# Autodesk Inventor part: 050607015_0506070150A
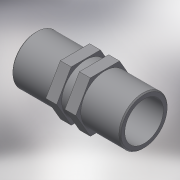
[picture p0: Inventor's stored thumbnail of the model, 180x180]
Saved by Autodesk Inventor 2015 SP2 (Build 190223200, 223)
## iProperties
Created: 2017-05
Part Number: 050607015_0506070150A
Material: Generic
Description: PLASSON NIPPLE 1.1/2"-1.1/2"
Document SubType Name: Modeling
Designer: KIM
Density: 1 g/cm^3
Appearance: Default
Author: KIM
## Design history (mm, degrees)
derived "050607.ipt"
feature "Solid1::050607.ipt"
tag "TaggingFeature1"
body "Solid1"
other parameters: "d0" = 61, "d1" = 47.803, "d3" = 38.2424, "d4" = 22, "d5" = 22, "d6" = 6.1, "d8" = 0.61, "d12" = 0, "H_" = 61, "R_" = 47.803, "l_2" = 22
